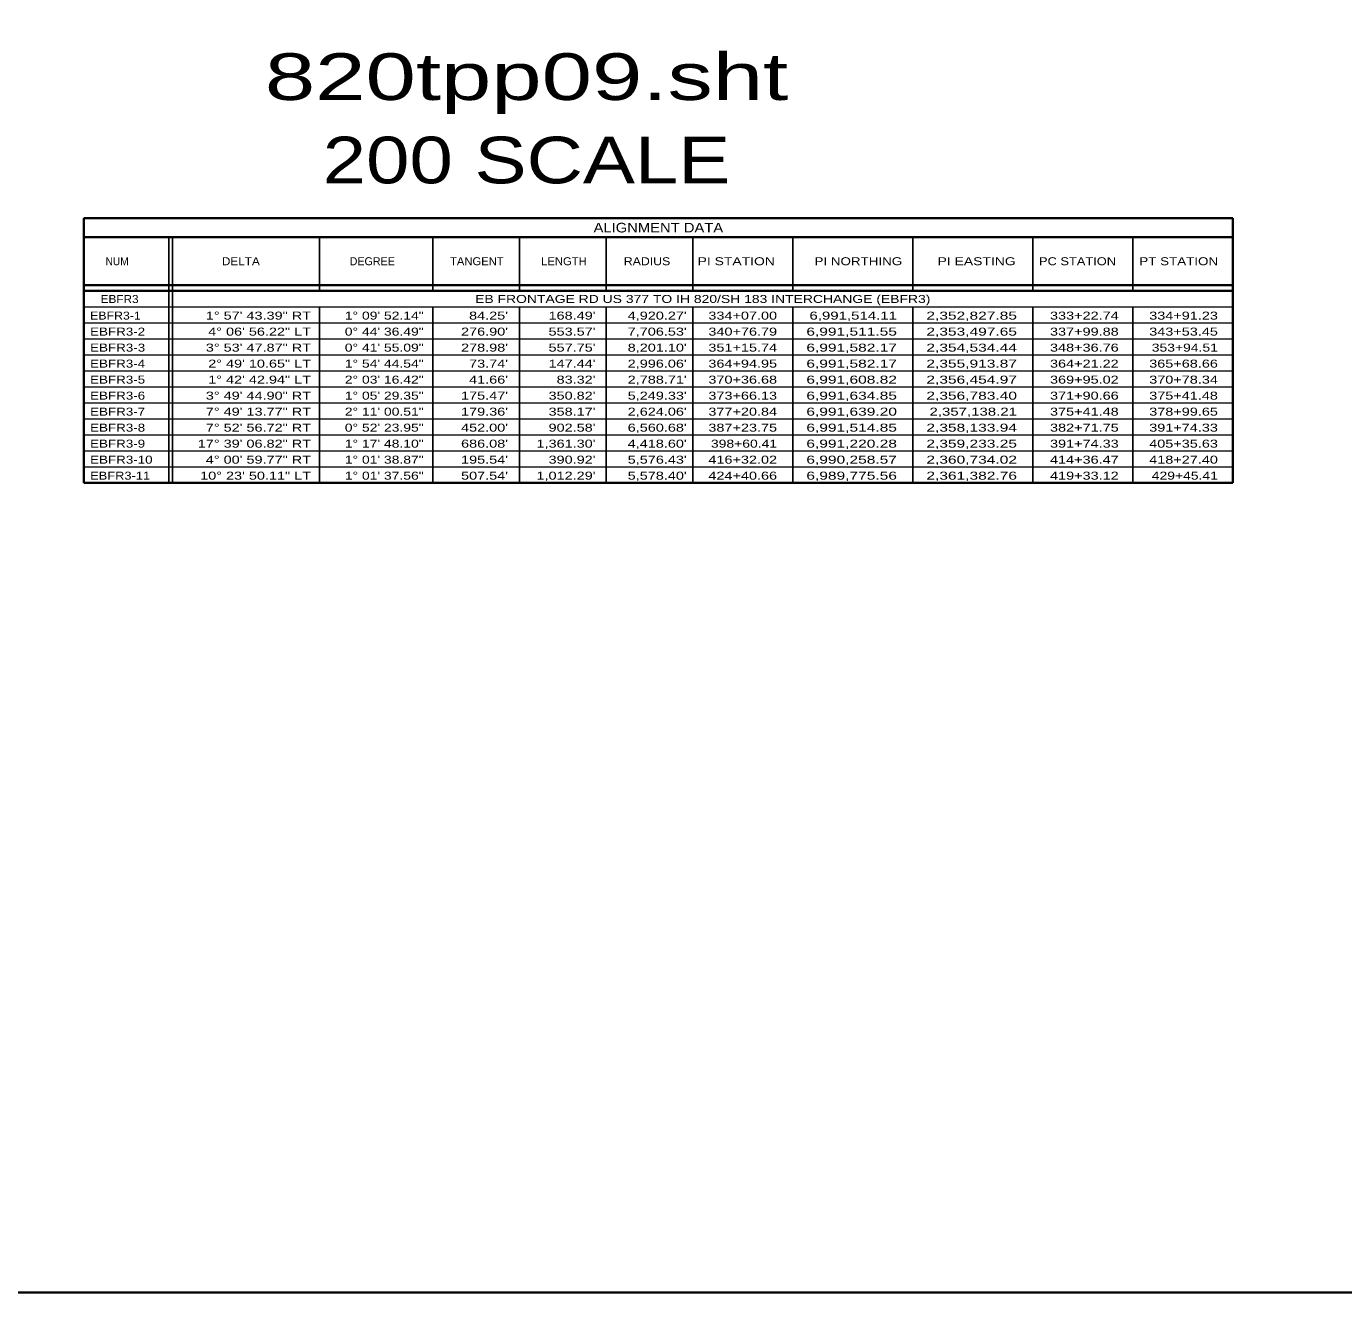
# Model space of a CAD drawing. Extents: x 1953053 to 1967065, y 7363860 to 7371201.
# Drawn here: x 1957841 to 1959817, y 7363860 to 7365759 of the extents above; entities that cross this region are included whole.
import ezdxf
from ezdxf.enums import TextEntityAlignment as Align

# ---------------------------------------------------------------- set-up
doc = ezdxf.new("R2010")
doc.units = 0
doc.header["$LTSCALE"] = 4.8
doc.layers.add('10', color=7, linetype='Continuous')
doc.layers.add('12', color=7, linetype='Continuous', lineweight=25)
doc.layers.add('62', color=7, linetype='Continuous', lineweight=35)

msp = doc.modelspace()

# ---------------------------------------------------------------- linework, layer by layer
at = {"layer": '12', "lineweight": 35}
for p, q in [((1959650.637, 7365471.266), (1957927.305, 7365471.266)), ((1957927.305, 7365471.266), (1957927.305, 7365074.133)), ((1959650.637, 7365074.133), (1959650.637, 7365471.266)), ((1957927.305, 7365442.466), (1959650.637, 7365442.466)), ((1957927.305, 7365370.466), (1959650.637, 7365370.466)), ((1957927.305, 7365362.133), (1959650.637, 7365362.133)), ((1957927.305, 7365074.133), (1959650.637, 7365074.133))]:
    msp.add_line(p, q, dxfattribs=at)
at = {"layer": '12'}
for p, q in [((1958055.15, 7365442.466), (1958055.15, 7365074.133)), ((1958060.637, 7365442.466), (1958060.637, 7365074.133)), ((1958280.637, 7365442.466), (1958280.637, 7365362.133)), ((1958450.637, 7365442.466), (1958450.637, 7365362.133)), ((1958580.637, 7365442.466), (1958580.637, 7365362.133)), ((1958710.637, 7365442.466), (1958710.637, 7365362.133)), ((1958840.637, 7365442.466), (1958840.637, 7365362.133)), ((1958990.637, 7365442.466), (1958990.637, 7365362.133)), ((1959170.637, 7365442.466), (1959170.637, 7365362.133)), ((1959350.637, 7365442.466), (1959350.637, 7365362.133)), ((1959500.637, 7365442.466), (1959500.637, 7365362.133)), ((1958055.15, 7365420.866), (1958055.15, 7365144.913)), ((1958280.637, 7365338.133), (1958280.637, 7365074.133)), ((1958450.637, 7365338.133), (1958450.637, 7365074.133)), ((1958580.637, 7365338.133), (1958580.637, 7365074.133)), ((1958710.637, 7365338.133), (1958710.637, 7365074.133)), ((1958840.637, 7365338.133), (1958840.637, 7365074.133)), ((1958990.637, 7365338.133), (1958990.637, 7365074.133)), ((1959170.637, 7365338.133), (1959170.637, 7365074.133)), ((1959350.637, 7365338.133), (1959350.637, 7365074.133)), ((1959500.637, 7365338.133), (1959500.637, 7365074.133))]:
    msp.add_line(p, q, dxfattribs=at)
at = {"layer": '12', "lineweight": 13}
for p, q in [((1957927.305, 7365338.133), (1959650.637, 7365338.133)), ((1957927.305, 7365314.133), (1959650.637, 7365314.133)), ((1957927.305, 7365290.133), (1959650.637, 7365290.133)), ((1957927.305, 7365266.133), (1959650.637, 7365266.133)), ((1957927.305, 7365242.133), (1959650.637, 7365242.133)), ((1957927.305, 7365218.133), (1959650.637, 7365218.133)), ((1957927.305, 7365194.133), (1959650.637, 7365194.133)), ((1957927.305, 7365170.133), (1959650.637, 7365170.133)), ((1957927.305, 7365146.133), (1959650.637, 7365146.133)), ((1957927.305, 7365122.133), (1959650.637, 7365122.133)), ((1957927.305, 7365098.133), (1959650.637, 7365098.133))]:
    msp.add_line(p, q, dxfattribs=at)
at = {"layer": '62'}
msp.add_lwpolyline([(1953052.784, 7371201.108), (1967065.314, 7371201.108), (1967065.314, 7363859.877), (1953052.784, 7363859.877)], close=True, dxfattribs=at)

# ---------------------------------------------------------------- texts
at = {"layer": '10'}
for s, width, p in [('EBFR3', 1.1, (1957952.711, 7365343.814)), ('EBFR3-1', 1.15, (1957936.926, 7365318.96)), ('EBFR3-2', 1.25, (1957936.926, 7365294.96)), ('EBFR3-3', 1.25, (1957936.926, 7365270.96)), ('EBFR3-4', 1.25, (1957936.926, 7365246.96)), ('EBFR3-5', 1.25, (1957936.926, 7365222.96)), ('EBFR3-6', 1.25, (1957936.926, 7365198.96)), ('EBFR3-7', 1.25, (1957936.926, 7365174.96)), ('EBFR3-8', 1.25, (1957936.926, 7365150.96)), ('EBFR3-9', 1.25, (1957936.926, 7365126.96)), ('EBFR3-10', 1.25, (1957936.926, 7365102.96)), ('EBFR3-11', 1.2, (1957936.926, 7365078.96))]:
    msp.add_text(s, height=12, dxfattribs=dict(at, width=width)).set_placement(p)
at = {"layer": '10', "width": 1.3}
msp.add_text('EB FRONTAGE RD US 377 TO IH 820/SH 183 INTERCHANGE (EBFR3)', height=12, dxfattribs=at).set_placement((1958855.637, 7365343.927), align=Align.CENTER)
at = {"layer": '10'}
for s, width, p in [('1° 57\' 43.39" RT', 1.35, (1958268.159, 7365318.96)), ('1° 09\' 52.14"', 1.3, (1958437.154, 7365318.96)), ("84.25'", 1.35, (1958563.564, 7365318.96)), ("168.49'", 1.35, (1958694.761, 7365318.96)), ("4,920.27'", 1.35, (1958831.53, 7365318.96)), ('334+07.00', 1.35, (1958967.074, 7365318.96)), ('6,991,514.11', 1.4, (1959146.839, 7365318.96)), ('2,352,827.85', 1.45, (1959326.839, 7365318.96)), ('333+22.74', 1.35, (1959479.417, 7365318.96)), ('334+91.23', 1.35, (1959628.149, 7365318.96)), ('4° 06\' 56.22" LT', 1.35, (1958268.159, 7365294.96)), ('0° 44\' 36.49"', 1.3, (1958437.154, 7365294.96)), ("276.90'", 1.35, (1958563.564, 7365294.96)), ("553.57'", 1.35, (1958694.761, 7365294.96)), ("7,706.53'", 1.35, (1958831.53, 7365294.96)), ('340+76.79', 1.35, (1958967.074, 7365294.96)), ('6,991,511.55', 1.45, (1959146.839, 7365294.96)), ('2,353,497.65', 1.45, (1959326.839, 7365294.96)), ('337+99.88', 1.35, (1959479.417, 7365294.96)), ('343+53.45', 1.35, (1959628.149, 7365294.96)), ('3° 53\' 47.87" RT', 1.35, (1958268.159, 7365270.96)), ('0° 41\' 55.09"', 1.3, (1958437.154, 7365270.96)), ("278.98'", 1.35, (1958563.564, 7365270.96)), ("557.75'", 1.35, (1958694.761, 7365270.96)), ("8,201.10'", 1.35, (1958831.53, 7365270.96)), ('351+15.74', 1.35, (1958967.074, 7365270.96)), ('6,991,582.17', 1.45, (1959146.839, 7365270.96)), ('2,354,534.44', 1.45, (1959326.839, 7365270.96)), ('348+36.76', 1.35, (1959479.417, 7365270.96)), ('353+94.51', 1.3, (1959628.149, 7365270.96)), ('2° 49\' 10.65" LT', 1.35, (1958268.159, 7365246.96)), ('1° 54\' 44.54"', 1.3, (1958437.154, 7365246.96)), ("73.74'", 1.35, (1958563.564, 7365246.96)), ("147.44'", 1.35, (1958694.761, 7365246.96)), ("2,996.06'", 1.35, (1958831.53, 7365246.96)), ('364+94.95', 1.35, (1958967.074, 7365246.96)), ('6,991,582.17', 1.45, (1959146.839, 7365246.96)), ('2,355,913.87', 1.45, (1959326.839, 7365246.96)), ('364+21.22', 1.35, (1959479.417, 7365246.96)), ('365+68.66', 1.35, (1959628.149, 7365246.96)), ('1° 42\' 42.94" LT', 1.35, (1958268.159, 7365222.96)), ('2° 03\' 16.42"', 1.3, (1958437.154, 7365222.96)), ("41.66'", 1.35, (1958563.564, 7365222.96)), ("83.32'", 1.35, (1958694.761, 7365222.96)), ("2,788.71'", 1.35, (1958831.53, 7365222.96)), ('370+36.68', 1.35, (1958967.074, 7365222.96)), ('6,991,608.82', 1.45, (1959146.839, 7365222.96)), ('2,356,454.97', 1.45, (1959326.839, 7365222.96)), ('369+95.02', 1.35, (1959479.417, 7365222.96)), ('370+78.34', 1.35, (1959628.149, 7365222.96)), ('3° 49\' 44.90" RT', 1.35, (1958268.159, 7365198.96)), ('1° 05\' 29.35"', 1.3, (1958437.154, 7365198.96)), ("175.47'", 1.35, (1958563.564, 7365198.96)), ("350.82'", 1.35, (1958694.761, 7365198.96)), ("5,249.33'", 1.35, (1958831.53, 7365198.96)), ('373+66.13', 1.35, (1958967.074, 7365198.96)), ('6,991,634.85', 1.45, (1959146.839, 7365198.96)), ('2,356,783.40', 1.45, (1959326.839, 7365198.96)), ('371+90.66', 1.35, (1959479.417, 7365198.96)), ('375+41.48', 1.35, (1959628.149, 7365198.96)), ('7° 49\' 13.77" RT', 1.35, (1958268.159, 7365174.96)), ('2° 11\' 00.51"', 1.3, (1958437.154, 7365174.96)), ("179.36'", 1.35, (1958563.564, 7365174.96)), ("358.17'", 1.35, (1958694.761, 7365174.96)), ("2,624.06'", 1.35, (1958831.53, 7365174.96)), ('377+20.84', 1.35, (1958967.074, 7365174.96)), ('6,991,639.20', 1.45, (1959146.839, 7365174.96)), ('2,357,138.21', 1.4, (1959326.839, 7365174.96)), ('375+41.48', 1.35, (1959479.417, 7365174.96)), ('378+99.65', 1.35, (1959628.149, 7365174.96)), ('7° 52\' 56.72" RT', 1.35, (1958268.159, 7365150.96)), ('0° 52\' 23.95"', 1.3, (1958437.154, 7365150.96)), ("452.00'", 1.35, (1958563.564, 7365150.96)), ("902.58'", 1.35, (1958694.761, 7365150.96)), ("6,560.68'", 1.35, (1958831.53, 7365150.96)), ('387+23.75', 1.35, (1958967.074, 7365150.96)), ('6,991,514.85', 1.45, (1959146.839, 7365150.96)), ('2,358,133.94', 1.45, (1959326.839, 7365150.96)), ('382+71.75', 1.35, (1959479.417, 7365150.96)), ('391+74.33', 1.35, (1959628.149, 7365150.96)), ('17° 39\' 06.82" RT', 1.35, (1958268.159, 7365126.96)), ('1° 17\' 48.10"', 1.3, (1958437.154, 7365126.96)), ("686.08'", 1.35, (1958563.564, 7365126.96)), ("1,361.30'", 1.35, (1958694.761, 7365126.96)), ("4,418.60'", 1.35, (1958831.53, 7365126.96)), ('398+60.41', 1.3, (1958967.074, 7365126.96)), ('6,991,220.28', 1.45, (1959146.839, 7365126.96)), ('2,359,233.25', 1.45, (1959326.839, 7365126.96)), ('391+74.33', 1.35, (1959479.417, 7365126.96)), ('405+35.63', 1.35, (1959628.149, 7365126.96)), ('4° 00\' 59.77" RT', 1.35, (1958268.159, 7365102.96)), ('1° 01\' 38.87"', 1.3, (1958437.154, 7365102.96)), ("195.54'", 1.35, (1958563.564, 7365102.96)), ("390.92'", 1.35, (1958694.761, 7365102.96)), ("5,576.43'", 1.35, (1958831.53, 7365102.96)), ('416+32.02', 1.35, (1958967.074, 7365102.96)), ('6,990,258.57', 1.45, (1959146.839, 7365102.96)), ('2,360,734.02', 1.45, (1959326.839, 7365102.96)), ('414+36.47', 1.35, (1959479.417, 7365102.96)), ('418+27.40', 1.35, (1959628.149, 7365102.96)), ('10° 23\' 50.11" LT', 1.35, (1958268.159, 7365078.96)), ('1° 01\' 37.56"', 1.3, (1958437.154, 7365078.96)), ("507.54'", 1.35, (1958563.564, 7365078.96)), ("1,012.29'", 1.35, (1958694.761, 7365078.96)), ("5,578.40'", 1.35, (1958831.53, 7365078.96)), ('424+40.66', 1.35, (1958967.074, 7365078.96)), ('6,989,775.56', 1.45, (1959146.839, 7365078.96)), ('2,361,382.76', 1.45, (1959326.839, 7365078.96)), ('419+33.12', 1.35, (1959479.417, 7365078.96)), ('429+45.41', 1.3, (1959628.149, 7365078.96))]:
    msp.add_text(s, height=12, dxfattribs=dict(at, width=width)).set_placement(p, align=Align.RIGHT)
at = {"layer": '12'}
for s, height, width, p in [('ALIGNMENT DATA', 14.4, 1.15, (1958789.078, 7365449.665)), ('NUM', 12, 0.95, (1957977.352, 7365400.462)), ('DELTA', 12, 1.1, (1958162.927, 7365400.465)), ('TANGENT', 12, 1.05, (1958516.825, 7365400.465)), ('LENGTH', 12, 1.05, (1958647.46, 7365400.465)), ('RADIUS', 12, 1.15, (1958772.07, 7365400.465)), ('PI STATION', 12, 1.3, (1958905.874, 7365400.465)), ('PI NORTHING', 12, 1.25, (1959088.95, 7365400.465)), ('PI EASTING', 12, 1.3, (1959266.341, 7365400.465)), ('PC STATION', 12, 1.2, (1959417.646, 7365400.465)), ('PT STATION', 12, 1.25, (1959569.417, 7365400.465))]:
    msp.add_text(s, height=height, dxfattribs=dict(at, width=width)).set_placement(p, align=Align.CENTER)
msp.add_text('DEGREE', height=12, dxfattribs=at).set_placement((1958360.014, 7365400.465), align=Align.CENTER)
at = {"layer": '62'}
for s, width, p in [('820tpp09.sht', 1.45, (1958591.36, 7365648.265)), ('200 SCALE', 1.25, (1958591.36, 7365523.265))]:
    msp.add_text(s, height=70, dxfattribs=dict(at, width=width)).set_placement(p, align=Align.CENTER)

doc.saveas('drawing.dxf')
